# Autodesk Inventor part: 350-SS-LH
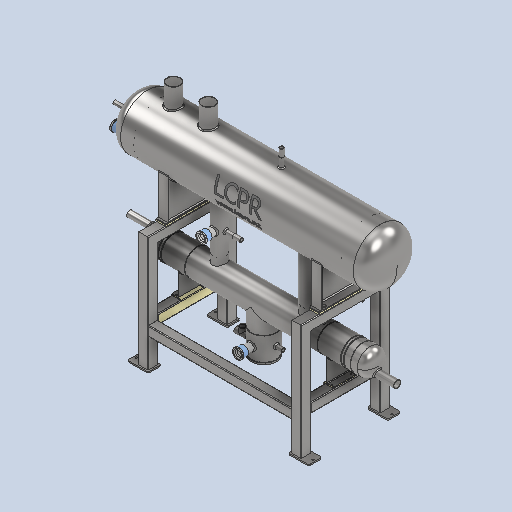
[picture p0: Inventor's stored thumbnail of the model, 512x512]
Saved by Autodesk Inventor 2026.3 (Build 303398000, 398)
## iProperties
Created: 2026-05
Part Number: 350-SS-LH
Material: Generic
Document SubType Name: Modeling
Designer: rva
Density: 1 g/cm^3
Appearance: Default
Author: rva
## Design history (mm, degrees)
derived "350-SS-LH.iam"
body "Solid1"
node "LPR-350-Frame Assembly.iam:1::LCPR-SS-350-135 x 85 Frame Foo"
node "LPR-350-Frame Assembly.iam:1::LCPR-SS-350-135 x 85 Frame Foo"
node "LPR-350-Frame Assembly.iam:1::LCPR-SS-350-135 x 85 Frame Foo"
node "LPR-350-Frame Assembly.iam:1::LCPR-SS-350-135 x 85 Frame Foo"
node "Sub-150-75-1171-30-40-32-SS-LH.iam:1::ISO 5251 Equal Tee DN1"
node "Sub-150-75-1171-30-40-32-SS-LH.iam:1::150-30-SS-Hole Sub Coo"
node "Sub-150-75-1171-30-40-32-SS-LH.iam:1::150-30-SS-Hole Sub Coo"
node "Sub-150-75-1171-30-40-32-SS-LH.iam:1::150 mm-SS- Subcooler L"
node "Sub-150-75-1171-30-40-32-SS-LH.iam:1::LCPR-150-SS-Blank Plat"
node "Sub-150-75-1171-30-40-32-SS-LH.iam:1::150 mm-SS- Subcooler L"
node "Sub-150-75-1171-30-40-32-SS-LH.iam:1::1-2 Inch NPT Socket - "
node "Sub-150-75-1171-30-40-32-SS-LH.iam:1::1-2 Inch NPT Socket - "
node "Sub-150-75-1171-30-40-32-SS-LH.iam:1::1-2 Inch NPT Socket - "
node "Sub-150-75-1171-30-40-32-SS-LH.iam:1::H1100-R.ipt:1"
node "Sub-150-75-1171-30-40-32-SS-LH.iam:1::H1100-R.ipt:2"
node "Sub-150-75-1171-30-40-32-SS-LH.iam:1::Welds"
node "Nylon Heat Tranfer Spacer 348x65.ipt:1"
node "Nylon Heat Tranfer Spacer 348x65.ipt:2"
node "AS 1111 - Metric M10 x 100:1"
node "AS 1112 (4) - Metric M10:1"
node "AS 1237 (4.1) 10 mm:1"
node "AS 1237 (4.1) 10 mm:2"
node "AS 1111 - Metric M10 x 100:2"
node "AS 1112 (4) - Metric M10:2"
node "AS 1237 (4.1) 10 mm:3"
node "AS 1237 (4.1) 10 mm:4"
node "AS 1111 - Metric M10 x 100:3"
node "AS 1112 (4) - Metric M10:3"
node "AS 1237 (4.1) 10 mm:5"
node "AS 1237 (4.1) 10 mm:6"
node "AS 1111 - Metric M10 x 100:4"
node "AS 1112 (4) - Metric M10:4"
node "AS 1237 (4.1) 10 mm:7"
node "AS 1237 (4.1) 10 mm:8"
node "350-SS-SHELL-WELD.iam:1::LCPR-LOGO.ipt:1"
node "350-SS-SHELL-WELD.iam:1::LCPR-SS-350-Leg Assembly.iam:1::Wel"
node "350-SS-SHELL-WELD.iam:1::LCPR-SS-350-Leg Assembly.iam:2::Wel"
node "350-SS-SHELL-WELD.iam:1::350 mm-SS- Dome End Cap.ipt:1"
node "350-SS-SHELL-WELD.iam:1::350 mm-SS- Dome End Cap.ipt:2"
node "350-SS-SHELL-WELD.iam:1::H1100-R.ipt:1"
node "350-SS-SHELL-WELD.iam:1::Welds"
node "Nylon Heat Tranfer Spacer 145x65.ipt:1"
node "Nylon Heat Tranfer Spacer 145x65.ipt:2"
node "350-SS-LH.iam_Bodies"
